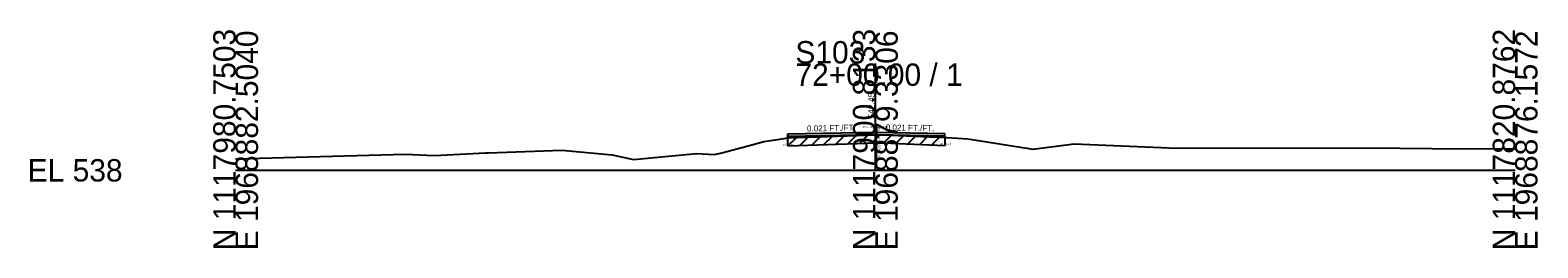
# Model space of a CAD drawing. Extents: x -26 to 163, y -10 to 24018.
# Drawn here: x -25.7 to 162.8, y 19990.3 to 20017.5 of the extents above; entities that cross this region are included whole.
import ezdxf

# ---------------------------------------------------------------- set-up
doc = ezdxf.new("R2010")
doc.units = 0
for name, color, linetype in [('RD_GPK_XS_Cell', 7, 'Continuous'), ('RD_XS_ExGround', 7, 'Continuous'), ('RD_XS_ExPaveRet', 7, 'Continuous'), ('RD_XS_Misc_Line', 7, 'Continuous'), ('RD_XS_PaveOvlay_CP', 7, 'Continuous'), ('RD_XS_TX_Elev_EX', 7, 'Continuous'), ('RD_XS_TX_ExEOP', 7, 'Continuous'), ('RD_XS_TX_Notes', 7, 'Continuous'), ('RD_XS_TX_Profile', 7, 'Continuous'), ('RD_XS_TX_Slope', 7, 'Continuous')]:
    doc.layers.add(name, color=color, linetype=linetype)

msp = doc.modelspace()

# ---------------------------------------------------------------- linework, layer by layer
at = {"layer": 'RD_GPK_XS_Cell'}
for p, q in [((80, 20000), (80, 20013.36)), ((0, 20000), (80, 20000)), ((80, 20000), (160, 20000))]:
    msp.add_line(p, q, dxfattribs=at)
at = {"layer": 'RD_XS_ExGround'}
msp.add_lwpolyline([(0, 20001.44), (21.21, 20002.03), (24.86, 20001.84), (31.25, 20002.17), (31.64, 20002.19), (40.81, 20002.5), (47.07, 20001.92), (49.76, 20001.37), (57.64, 20002.1), (59.9, 20001.96), (60.82, 20002.17), (64.54, 20003.2), (66.07, 20003.62), (68.61, 20003.99), (69.04, 20004.05), (78.98, 20004.41), (80.11, 20004.45), (80.97, 20004.42), (88.68, 20004.12), (88.98, 20004.11), (91.57, 20003.95), (98.95, 20002.75), (99.63, 20002.63), (100.04, 20002.69), (104.84, 20003.3), (117.69, 20002.78), (141.63, 20002.83), (149.6, 20002.73), (160, 20002.69)], dxfattribs=at)
at = {"layer": 'RD_XS_ExPaveRet'}
for p, q in [((69.04, 20003.05), (70.08, 20004.08)), ((69.04, 20003.05), (69.04, 20004.05)), ((69.04, 20003.05), (78.98, 20003.41)), ((70.54, 20003.1), (71.58, 20004.14)), ((72.04, 20003.16), (73.08, 20004.2)), ((73.54, 20003.21), (74.58, 20004.25)), ((75.04, 20003.27), (76.08, 20004.31)), ((76.54, 20003.32), (77.58, 20004.36)), ((78.04, 20003.38), (79.08, 20004.42)), ((78.98, 20003.41), (80.11, 20003.45)), ((79.54, 20003.43), (80.54, 20004.44)), ((80.11, 20003.45), (80.97, 20003.42)), ((80.97, 20003.42), (88.68, 20003.12)), ((81.04, 20003.42), (82, 20004.38)), ((82.54, 20003.36), (83.5, 20004.32)), ((84.04, 20003.3), (85, 20004.27)), ((85.54, 20003.24), (86.5, 20004.21)), ((87.04, 20003.19), (88, 20004.15)), ((88.68, 20004.12), (88.68, 20003.12))]:
    msp.add_line(p, q, dxfattribs=at)
at = {"layer": 'RD_XS_Misc_Line'}
msp.add_line((80.11, 20004.45), (80.11, 20001.45), dxfattribs=at)
at = {"layer": 'RD_XS_PaveOvlay_CP'}
for p, q in [((69.04, 20004.55), (80, 20004.78)), ((69.04, 20004.05), (69.04, 20004.55)), ((80, 20004.45), (69.04, 20004.22)), ((80, 20004.78), (88.68, 20004.6)), ((88.68, 20004.27), (80, 20004.45)), ((88.68, 20004.12), (88.68, 20004.6))]:
    msp.add_line(p, q, dxfattribs=at)

# ---------------------------------------------------------------- texts
at = {"layer": 'RD_GPK_XS_Cell'}
for s, p in [('N 1117980.7503', (0, 19990)), ('E 1968882.5040', (2.8, 19990)), ('N 1117900.8133', (80, 19990)), ('E 1968879.3306', (82.8, 19990)), ('N 1117820.8762', (160, 19990)), ('E 1968876.1572', (162.8, 19990))]:
    msp.add_text(s, height=2.8, rotation=90, dxfattribs=at).set_placement(p)
for s, p in [('S103', (70, 20013.36)), ('72+00.00 / 1', (70, 20010.56)), ('EL 538', (-26, 19998.6))]:
    msp.add_text(s, height=2.8, dxfattribs=at).set_placement(p)
at = {"layer": 'RD_XS_TX_Elev_EX'}
msp.add_text('542.45', height=0.8, rotation=90, dxfattribs=at).set_placement((79.9, 20006.45))
at = {"layer": 'RD_XS_TX_ExEOP'}
for s, p in [('EOP-L', (68.99, 20004.55)), ('EOP-R', (88.63, 20004.6))]:
    msp.add_text(s, height=0.1, rotation=270, dxfattribs=at).set_placement(p)
at = {"layer": 'RD_XS_TX_Notes'}
for s, p in [('Elev. @CL = 542.78', (78.48, 20005.28)), (' dE= 0.50', (68.32, 20003.05)), (' dE= 0.33', (79.29, 20003.45)), (' dE= 0.47', (87.97, 20003.12))]:
    msp.add_text(s, height=0.25, dxfattribs=at).set_placement(p)
msp.add_text(' Min. Distance @CP = -0.01', height=0.25, rotation=270, dxfattribs=at).set_placement((80.36, 20005.54))
at = {"layer": 'RD_XS_TX_Profile'}
msp.add_text('CL', height=0.25, dxfattribs=at).set_placement((79.77, 20004.78))
at = {"layer": 'RD_XS_TX_Slope'}
for rotation, p in [(1.1916, (71.46, 20004.85)), (358.8084, (81.29, 20005))]:
    msp.add_text('0.021 FT./FT.', height=0.75, rotation=rotation, dxfattribs=at).set_placement(p)

doc.saveas('drawing.dxf')
